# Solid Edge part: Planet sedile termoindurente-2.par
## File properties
Author: s.pallini
Template: Normal.par
Last saved by: s.pallini
Revision: 7
Application: Solid Edge
Precisione: 0,990
Tipo di contenuto documento: 0
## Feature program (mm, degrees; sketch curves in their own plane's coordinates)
sketch for "ExtrudedProtrusion_1" plane through (0, 0, 0) normal (0, -1, 0) x-axis (1, 0, 0)
  line (-120, -215) -> (120, -215)
  line (120, -215) -> (120, -173.8534)
  arc centre (200, -173.8534) radius 80 from (139.6226, -121.3693) to (120, -173.8534) ccw
  arc centre (-200, -173.8534) radius 80 from (-120, -173.8534) to (-139.6226, -121.3693) ccw
  line (-120, -215) -> (-120, -173.8534)
  dimension (linear) = 120
extrude "ExtrudedProtrusion_1" add finite 20 along -normal
draft "Draft_1"  Angles1 = 10 deg
thinwall "Thinwall_1"  Thickness = 5 mm
fillet "Rotondo_1" radius 5
fillet "Rotondo_2" radius 3
sketch for "unnamed Cutout 1" plane through (0, 0, -17.361) normal (0, -1, 0) x-axis (-1, 0, 0)
extrude "unnamed Cutout 1" cut through along -normal
sketch for "ExtrudedProtrusion_3" #1 plane through (0, 5, -18.861) normal (0, 1, 0) x-axis (1, 0, 0)
  circle centre (0, -18.861) radius 130
sketch for "ExtrudedProtrusion_3" #2 plane through (0, 5, -18.861) normal (0, 1, 0) x-axis (1, 0, 0)
extrude "ExtrudedProtrusion_3" add finite 20 along +normal
fillet "Rotondo_4" radius 10
fillet "Rotondo_5" radius 5
fillet "Rotondo_6" radius 5
sketch for "ExtrudedProtrusion_4" #1 plane through (0, 11.5, -215) normal (0, 0, -1) x-axis (1, 0, 0)
sketch for "ExtrudedProtrusion_4" #2 plane through (0, 11.5, -215) normal (0, 0, -1) x-axis (1, 0, 0)
extrude "ExtrudedProtrusion_4" add finite 35 along +normal
sketch for "unnamed Protrusion 1" plane through (-73, 10.0846, -232.5) normal (-1, 0, 0) x-axis (0, 0, -1)
  line (-17.5, 9.9154) -> (7.5, 20)
  line (7.5, 20) -> (17.5, 20)
  line (17.5, 9.9154) -> (17.5, 20)
  line (-17.5, 9.9154) -> (17.5, 9.9154)
extrude "unnamed Protrusion 1" add to key point along -normal
sketch for "ExtrudedProtrusion_6" plane through (73, 10.0846, -232.5) normal (1, 0, 0) x-axis (0, -1, 0)
  line (10, 17.5) -> (10, -17.2904)
  line (10, -17.2904) -> (20, 7.5)
  line (20, 7.5) -> (20, 17.5)
  line (20, 17.5) -> (10, 17.5)
extrude "ExtrudedProtrusion_6" add finite 25 along -normal
sketch for "ExtrudedProtrusion_7" #1 plane through (0, 25, -15) normal (0, 1, 0) x-axis (0, 0, -1)
  circle centre (-94.6781, -150.1712) radius 15
sketch for "ExtrudedProtrusion_7" #2 plane through (0, 25, -15) normal (0, 1, 0) x-axis (0, 0, -1)
  circle centre (64.6781, 150.1712) radius 15
sketch for "ExtrudedProtrusion_7" #3 plane through (0, 25, -15) normal (0, 1, 0) x-axis (0, 0, -1)
  circle centre (-94.6781, 150.1712) radius 15
sketch for "ExtrudedProtrusion_7" #4 plane through (0, 25, -15) normal (0, 1, 0) x-axis (0, 0, -1)
  circle centre (64.6781, -150.1712) radius 15
extrude "ExtrudedProtrusion_7" add through along -normal  Profile_Plane1_Distance = 5 mm
fillet "Rotondo_11" radius 5
fillet "Rotondo_12" radius 3
fillet "Rotondo_13" radius 15
fillet "Rotondo_14" radius 10
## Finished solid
Body 1: solid body, 103 faces, 238 edges, 136 vertices.
  Faces by surface: plane 35, torus 22, cylinder 20, blend 16, cone 10
  Edges by curve: circle 108, line 84, intersection 40, ellipse 6
Bounding box of the edges (mm; curved faces can reach further): 370.000 x 33.739 x 435.000, from (-185, -8.7393, -250) to (185, 25, 185).
Cylindrical faces by radius (mm): R3 x3, R5 x5, R10 x2, R15 x8, R130 x1, R135 x1
Conical faces (half-angle, radius in mm at the cone's reference point): 10 deg R80 x2, 10 deg R84.924 x2, 10 deg R180.076 x5, 10 deg R185 x1
Toroidal faces (ring radius, tube radius in mm): R2 r3 x2, R10 r5 x4, R18 r3 x4, R87.722 r5 x2, R91.9175 r5 x2, R140 r5 x1, R140 r10 x1, R173.0825 r5 x5, R177.278 r5 x1
Planar faces by outward normal: +x 2, +y 12, +z 5, -x 2, -y 3, -z 5, oblique 6
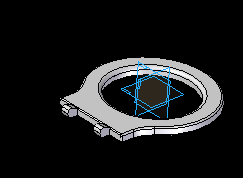
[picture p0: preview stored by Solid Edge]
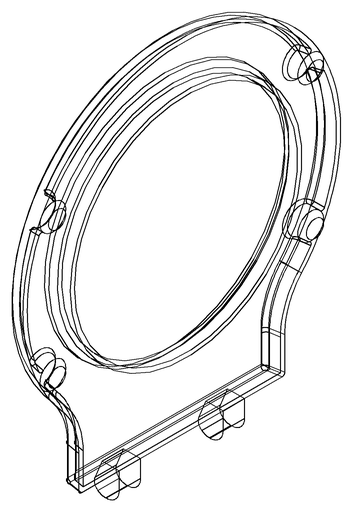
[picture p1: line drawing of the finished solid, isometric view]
